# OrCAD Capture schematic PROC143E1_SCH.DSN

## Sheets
1 05. ACCESSORIES: title: HARDWARE SCHEMATICS; rev: E1
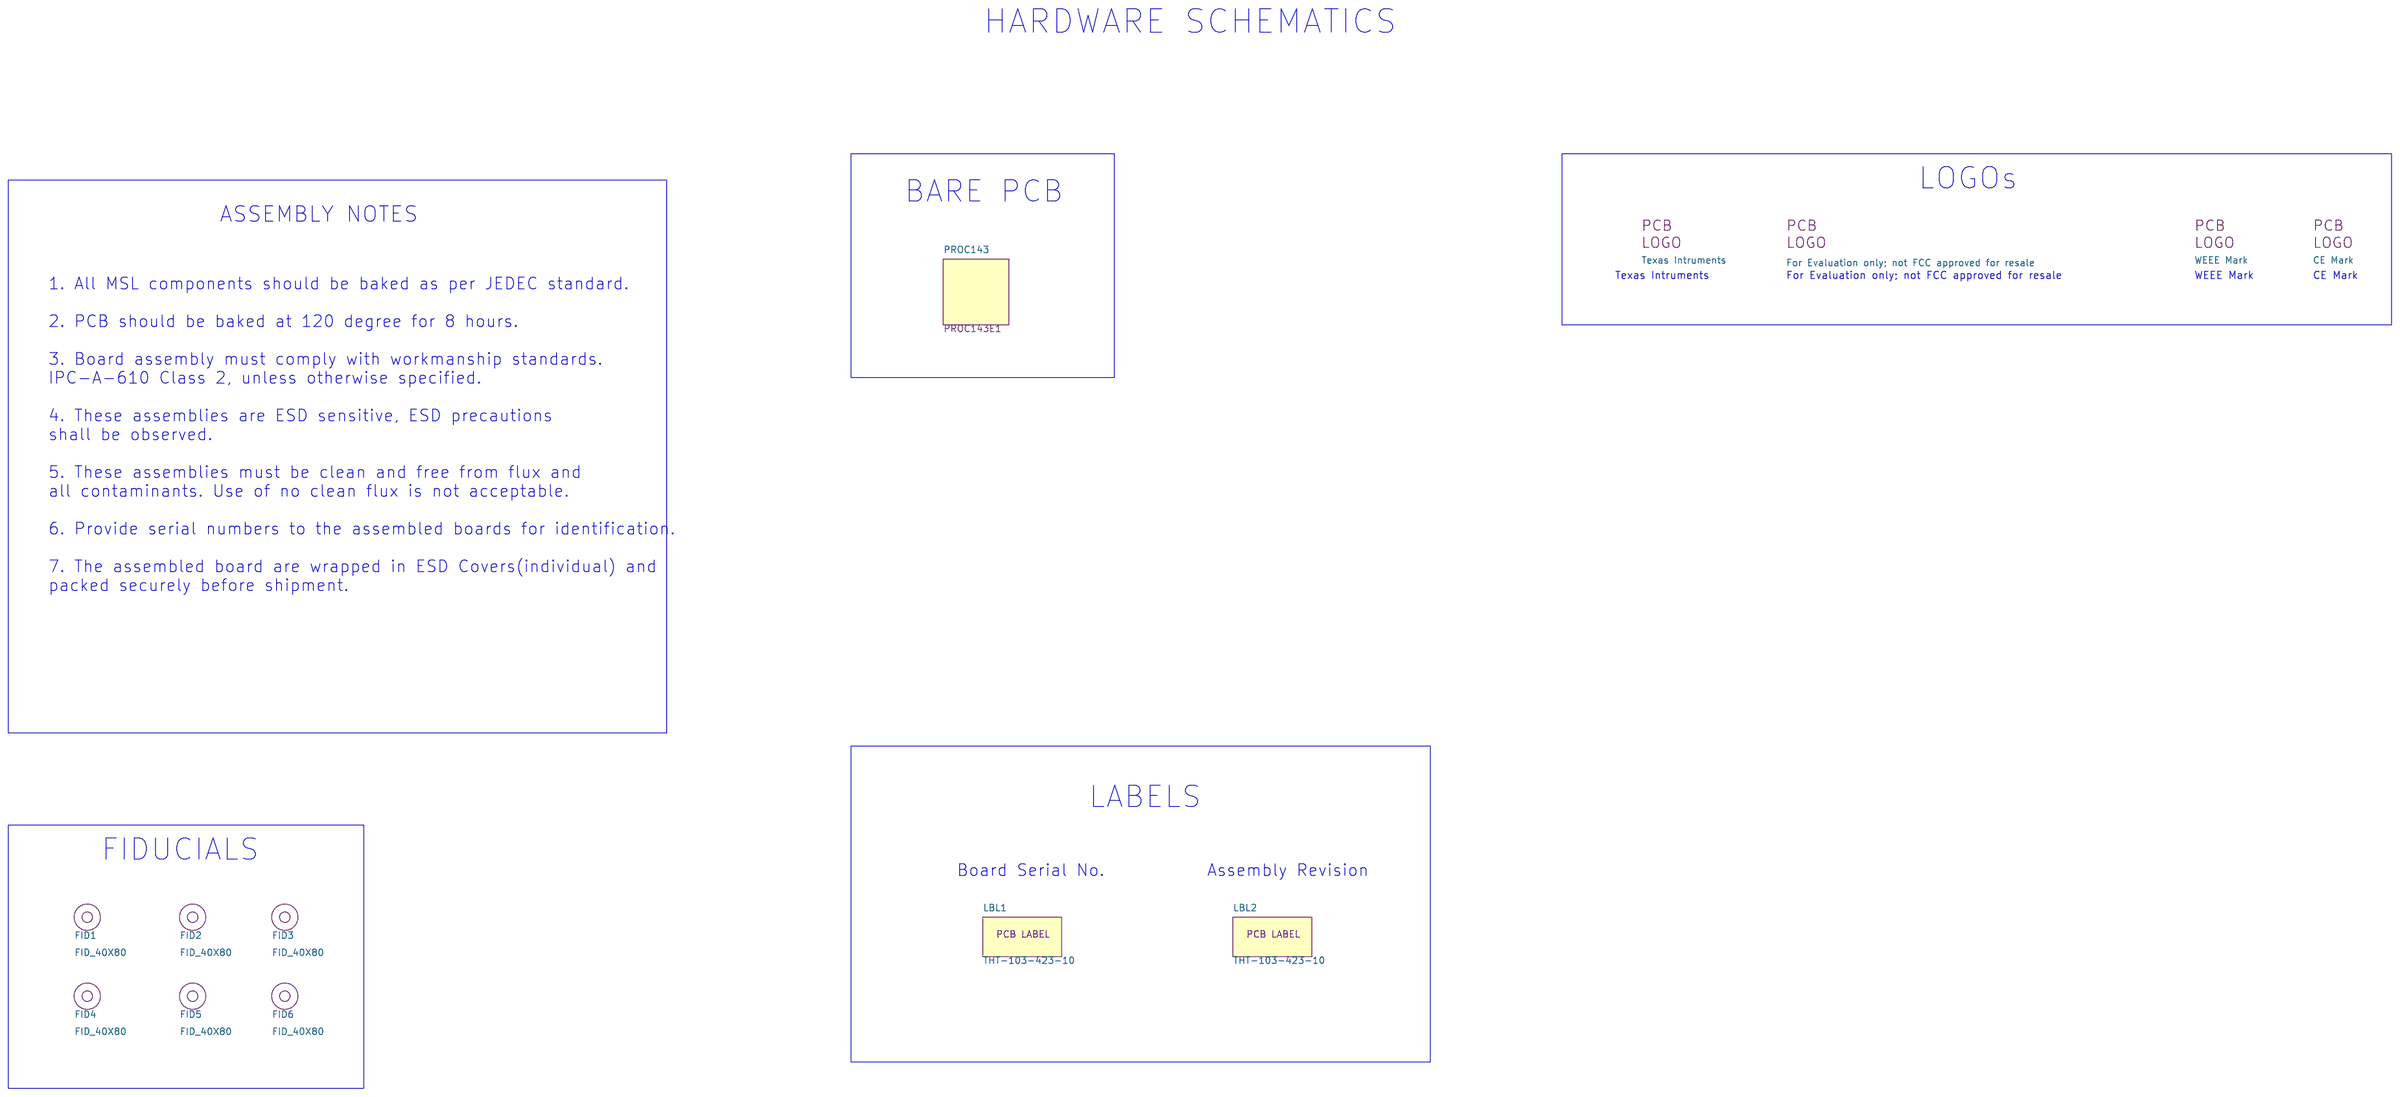
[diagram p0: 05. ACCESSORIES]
2 01. TABLE OF CONTENTS: title: TABLE OF CONTENTS
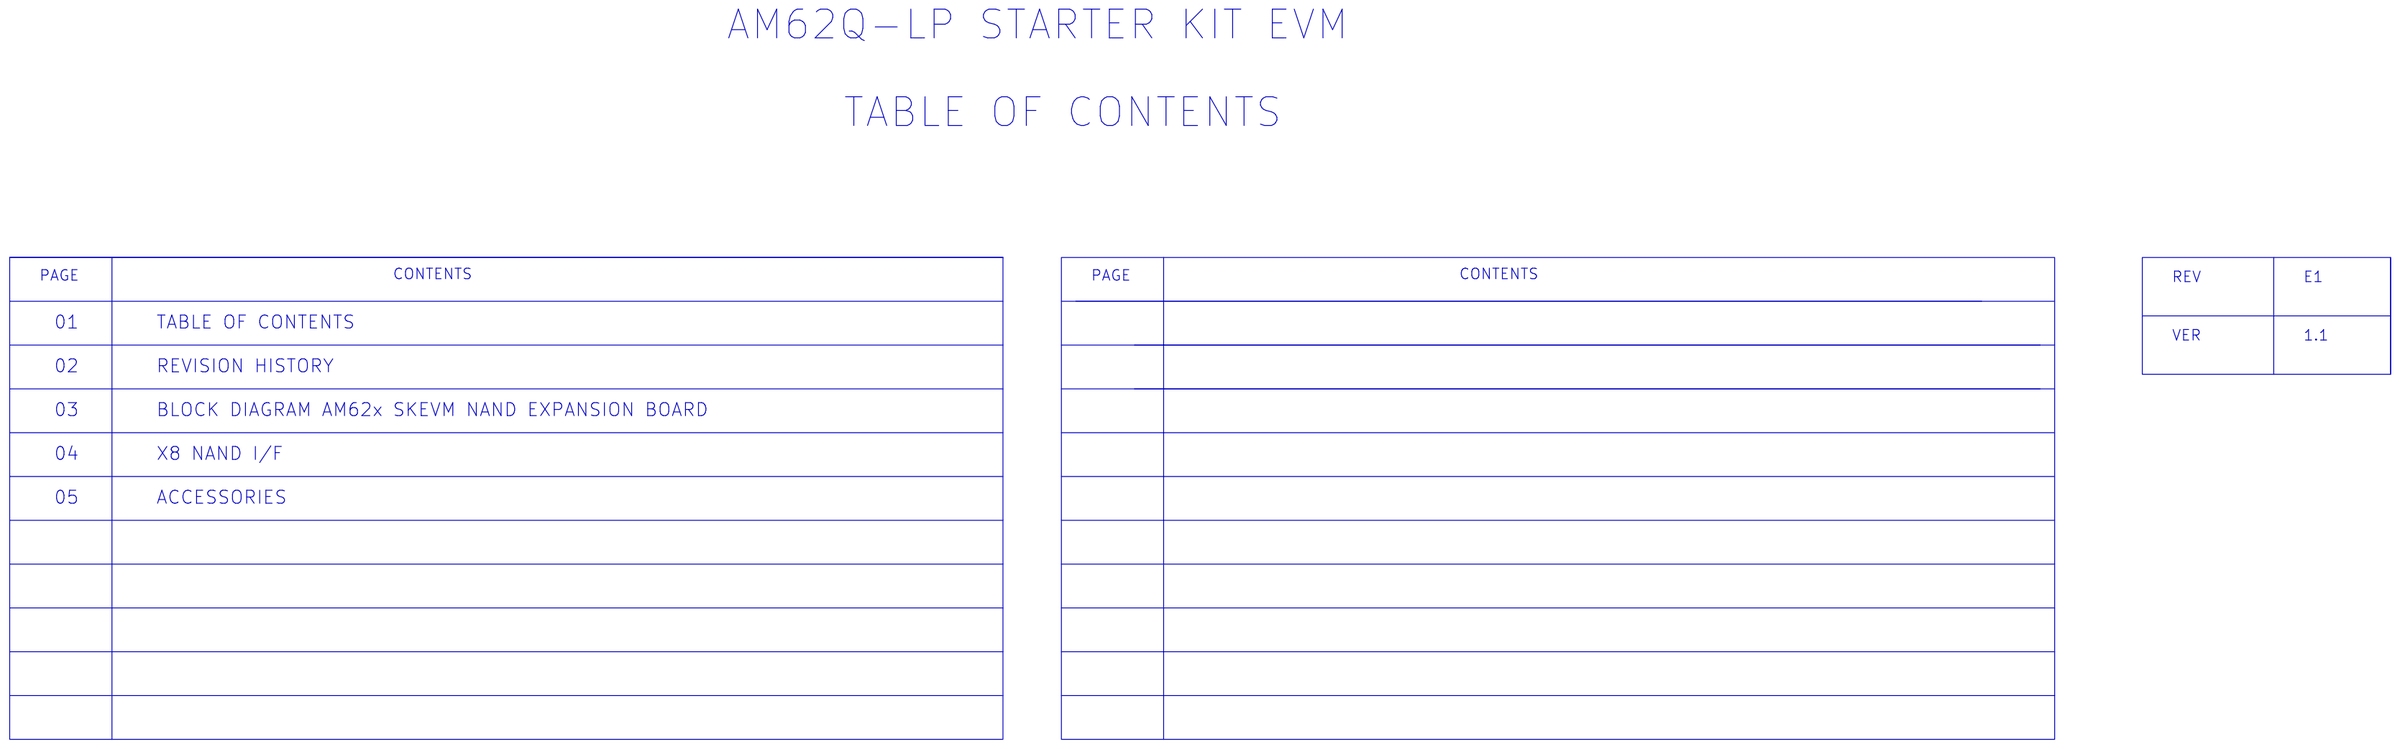
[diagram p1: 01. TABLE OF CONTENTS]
3 02. REVISION HISTORY: title: REVISION HISTORY
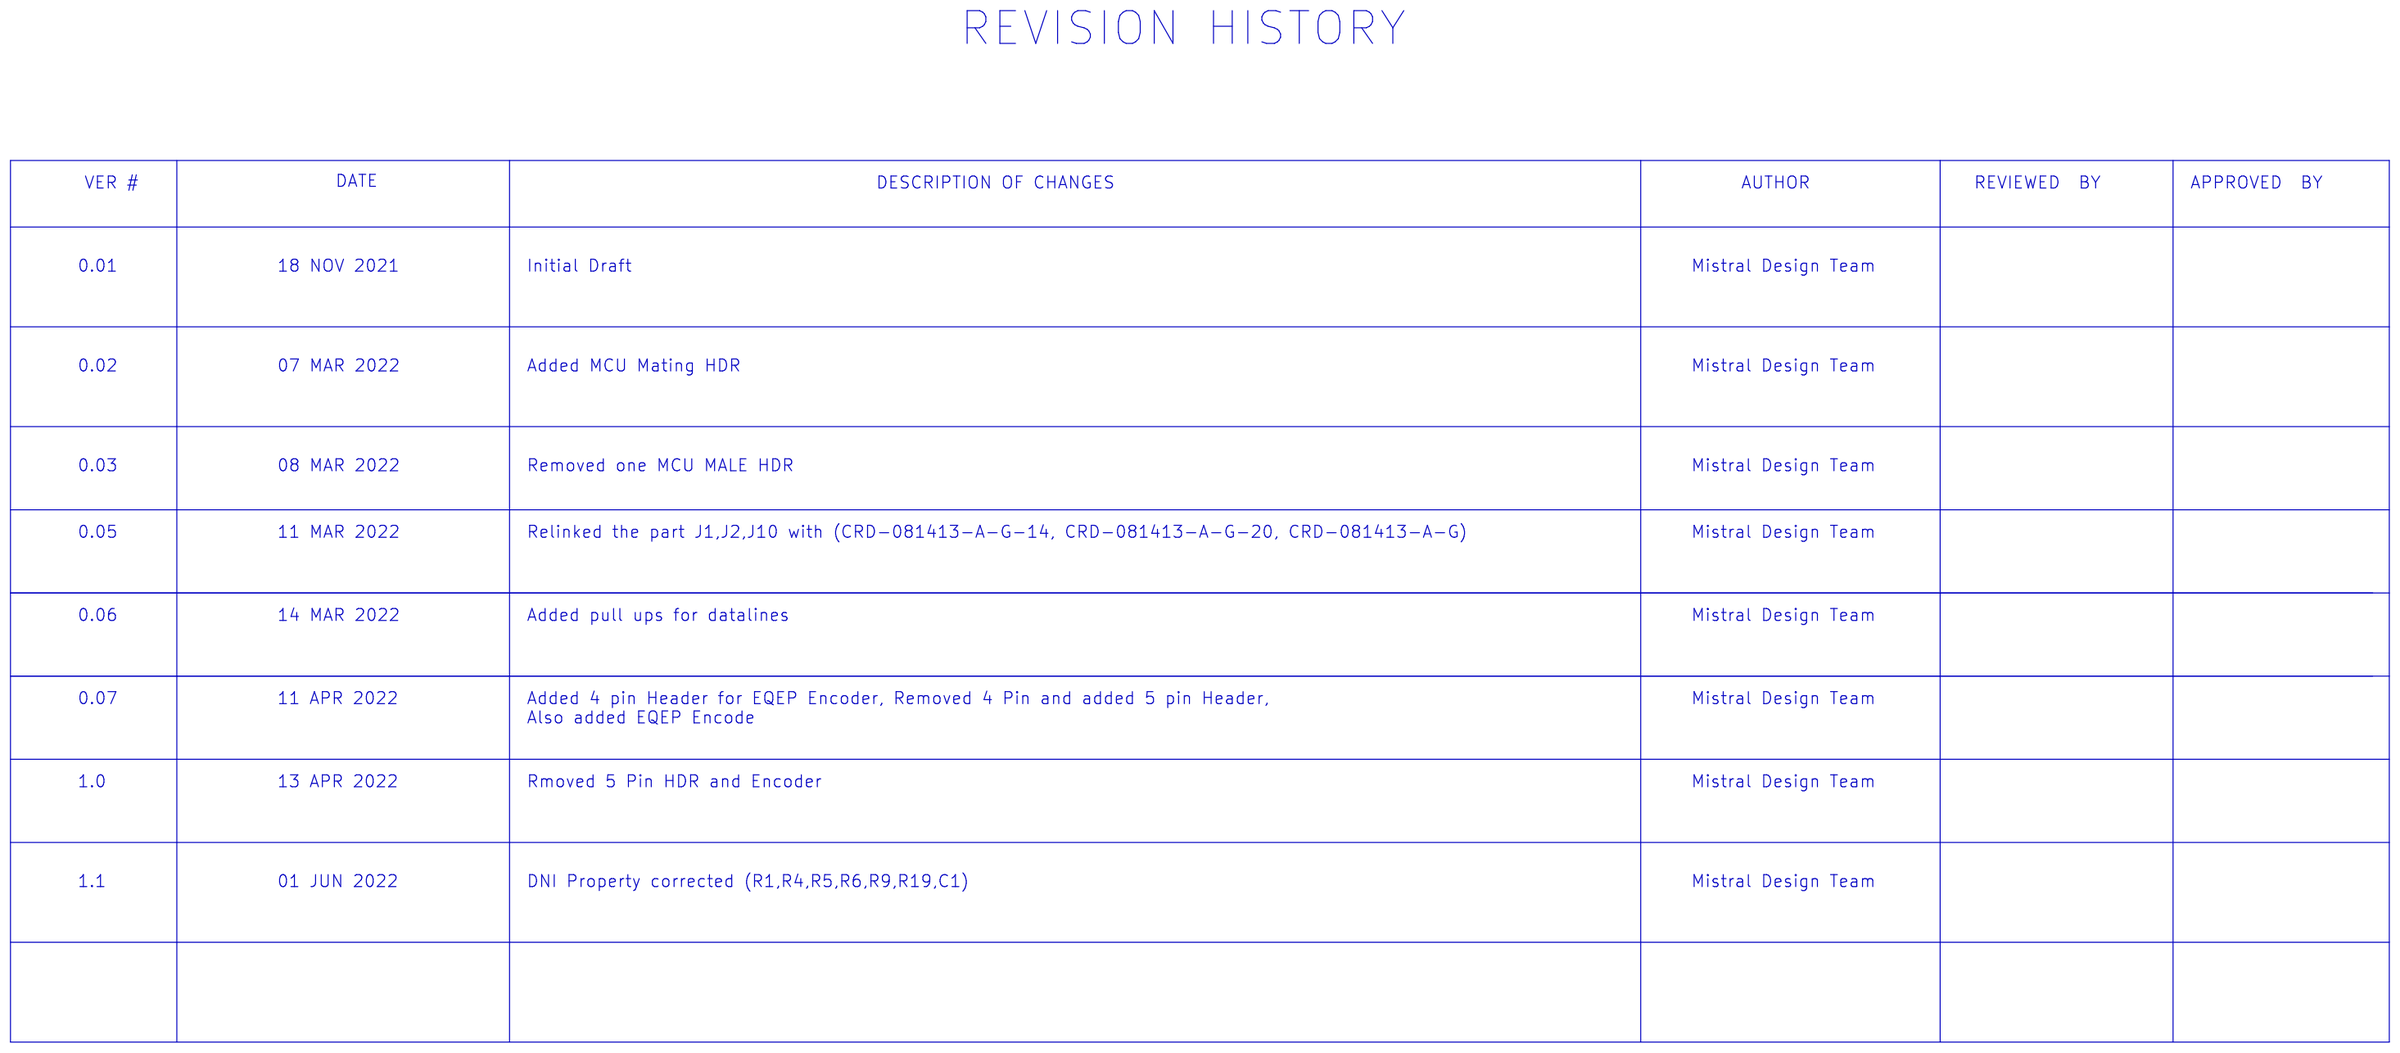
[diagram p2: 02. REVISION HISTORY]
4 03. BLOCK DGM AM62Q-LP-SKEVM: title: BLOCK DIAGRAM x8 NAND
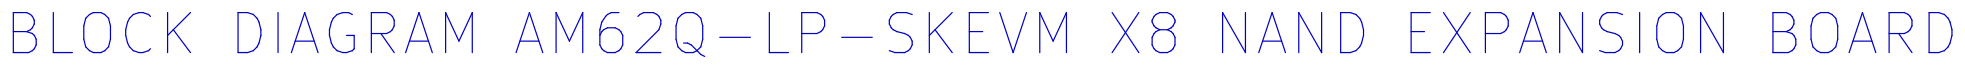
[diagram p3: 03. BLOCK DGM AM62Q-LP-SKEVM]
5 04. X8 NAND I/F: size C; title: x8 NAND
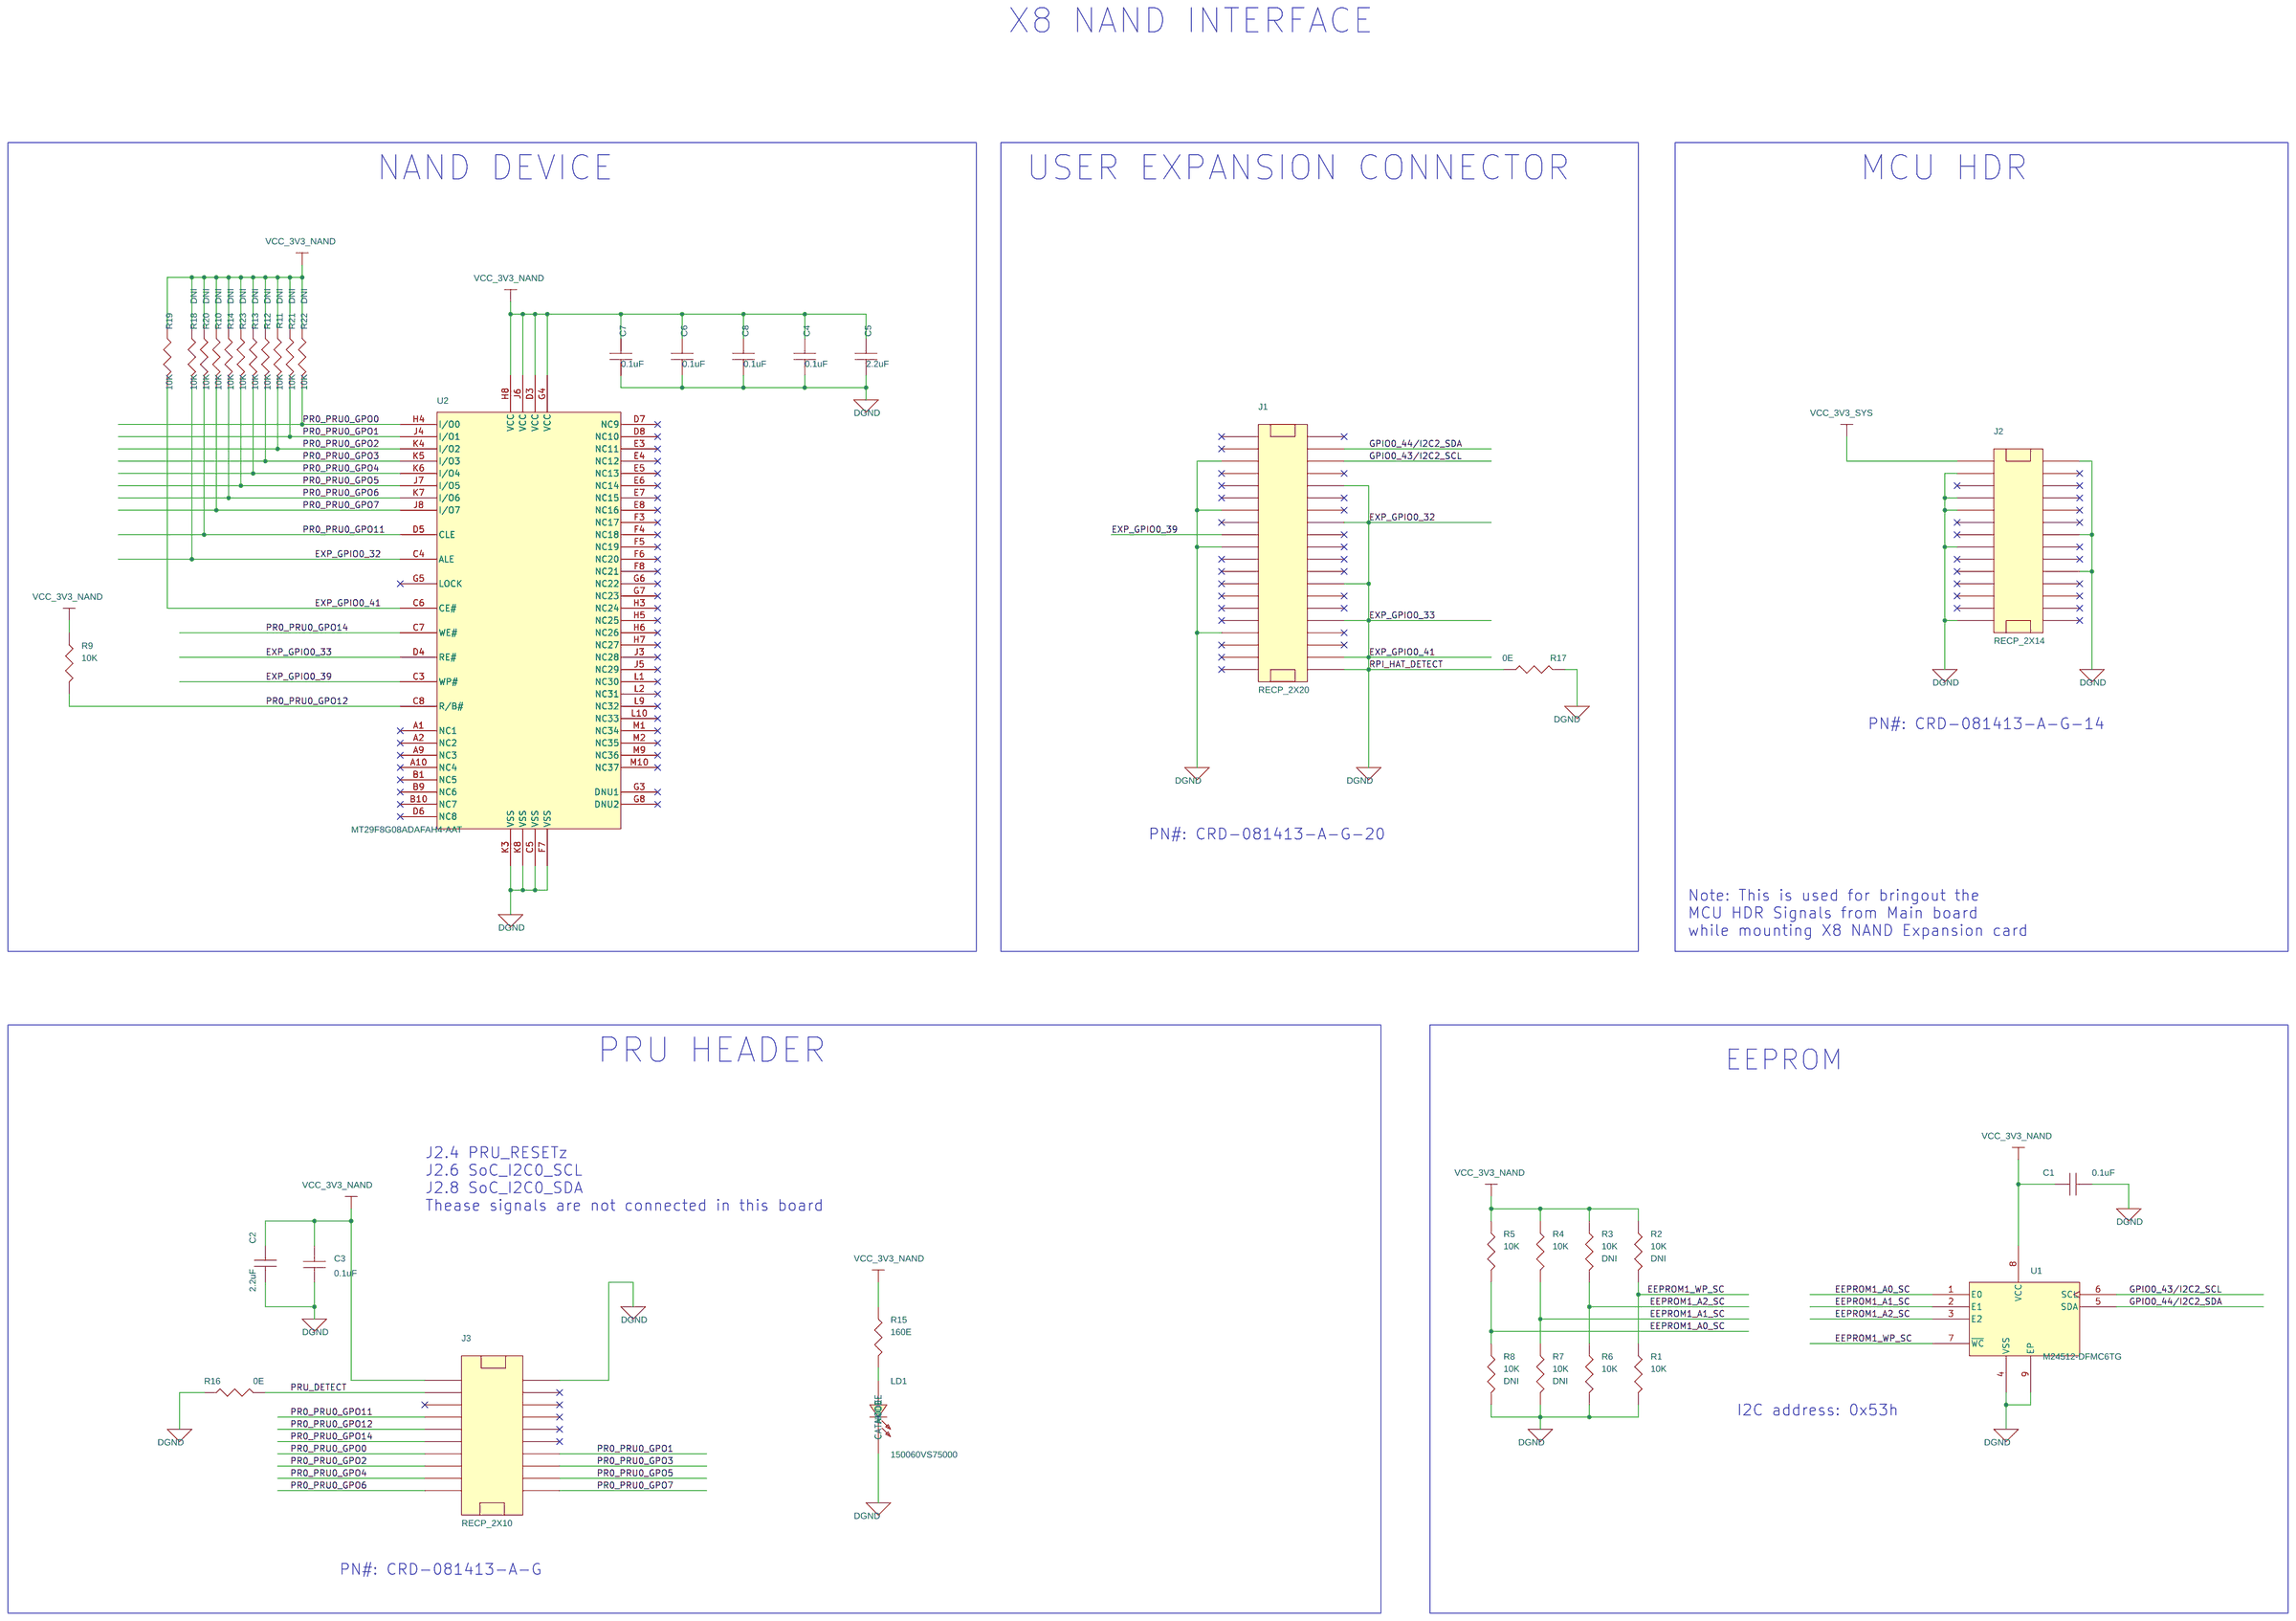
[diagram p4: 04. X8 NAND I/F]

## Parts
sheet 04. X8 NAND I/F
C1  0.1uF  [CAP0402_0-75]
C2  2.2uF  [CAP0402_0-75]
C3  0.1uF  [CAP0402_0-75]
C4  0.1uF  [CAP0402_0-75]
C5  2.2uF  [CAP0402_0-75]
C6  0.1uF  [CAP0402_0-75]
C7  0.1uF  [CAP0402_0-75]
C8  0.1uF  [CAP0402_0-75]
J1  RECP_2X20  [RECPT_2X20_CRD-081413-A-20_S_T_8-6]
J2  RECP_2X14  [RECPT_2X14_CRD-081413-A-14_S_T_8-6]
J3  RECP_2X10  [RECPT_2X10_CRD-081413-A_S_T_8-6]
LD1  150060VS75000  [LED_150060SS75000_70X40_SMD_0-8]
R1  10K  [RES0402_0-5]
R2  10K  [RES0402_0-5]
R3  10K  [RES0402_0-5]
R4  10K  [RES0402_0-5]
R5  10K  [RES0402_0-5]
R6  10K  [RES0402_0-5]
R7  10K  [RES0402_0-5]
R8  10K  [RES0402_0-5]
R9  10K  [RES0402_0-5]
R10  10K  [RES0402_0-5]
R11  10K  [RES0402_0-5]
R12  10K  [RES0402_0-5]
R13  10K  [RES0402_0-5]
R14  10K  [RES0402_0-5]
R15  160E  [RES0603_0-75]
R16  0E  [RES0201_0-5]
R17  0E  [RES0201_0-5]
R18  10K  [RES0402_0-5]
R19  10K  [RES0402_0-5]
R20  10K  [RES0402_0-5]
R21  10K  [RES0402_0-5]
R22  10K  [RES0402_0-5]
R23  10K  [RES0402_0-5]
U1  M24512-DFMC6TG  [UFDFPN8_M24512_120X80_0-6]
U2  MT29F8G08ADAFAH4-AAT  [FBGA63_31-49_360X440_1]
sheet 05. ACCESSORIES
FID1  FID_40X80  [FID_40X80]
FID2  FID_40X80  [FID_40X80]
FID3  FID_40X80  [FID_40X80]
FID4  FID_40X80  [FID_40X80]
FID5  FID_40X80  [FID_40X80]
FID6  FID_40X80  [FID_40X80]
LBL1  THT-103-423-10  [NA]
LBL2  THT-103-423-10  [NA]
LOGO1  Texas Intruments  [TI_Stacked_Overlay_Small]
LOGO2  For Evaluation only; not FCC approved for resale  [FCC_disclaimer]
LOGO3  WEEE Mark  [TI_Stacked_Overlay_Small]
LOGO4  CE Mark  [TI_Stacked_Overlay_Small]
PCB1  PROC143

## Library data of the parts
C1 C3 C4 C6-C8 = CAP: CAP CERAMIC 0.1uF 25V 20% X5R 0402; Chkd/date: MANIRAJA/170820; Crtd /date: ALVY/170820; Custom_Duty: 15%; Customs_HS_Code: 85322990; Distributor_name: DIGIKEY; Distributor_part_number: 732-7495-1-ND; Footprint Path: Y:\MIS_DATABASE\Library\ALTIUM_TOOL\PCB_FOOTPRINTS\Altium_Footprint_Lib.PcbLib; Height: 0.55MM; Library Path: Y:\MIS_DATABASE\Library\ALTIUM_TOOL\SCHEMATICS_PARTS\MS_DISCRETE_Library.schlib; Mfr_name: WURTH ELECTRONICS; Mfr_part_number: 885012105018; Mistral Part No: 120020080003-R; Package: 0402; Part_type: CAPACITORS\CERAMIC; Project: AM64x_EVM_BRD; RoHS: RoHS; Temperature: -55°C+85°C; Tolerance: 20%; Voltage: 25V; Wattage: NA; Weight: 0.65mg; Datasheet: Y:\MIS_DATABASE\DATASHEETS\CAPACITORS\885012105018.PDF
C2 C5 = CAP: CAP CERAMIC 2.2uF 25V 10% X5R 0402; Chkd/date: ALVY/010721; Crtd /date: MANIRAJA/010721; Custom_Duty: 15%; Customs_HS_Code: 85322990; Distributor_name: DIGIKEY; Distributor_part_number: 490-12703-1-ND; Footprint Path: Y:\MIS_DATABASE\Library\ALTIUM_TOOL\PCB_FOOTPRINTS\Altium_Footprint_Lib.PcbLib; Height: 0.70MM; Library Path: Y:\MIS_DATABASE\Library\ALTIUM_TOOL\SCHEMATICS_PARTS\MS_DISCRETE_Library.schlib; Mfr_name: MURATA; Mfr_part_number: GRM155R61E225KE11D; Mistral Part No: 120015120001-R; Package: 0402; Part_type: CAPACITORS\CERAMIC; Project: TI_AM263X_CC; RoHS: RoHS; Temperature: -55°C+85°C; Tolerance: 10%; Voltage: 25V; Wattage: NA; Weight: 1.5mg; Datasheet: Y:\MIS_DATABASE\DATASHEETS\CAPACITORS\GRM155R61E225KE11.PDF
J1 = RECP_20X2: CON RECP 2X20 2.54MM PITCH ST TH; Chkd/date: ALVY/110322; Crtd /date: TAMILARASU/100322; Custom_Duty: 24%; Customs_HS_Code: 85369090; Distributor_name: NA; Distributor_part_number: NA; Footprint Path: Y:\MIS_DATABASE\Library\ALTIUM_TOOL\PCB_FOOTPRINTS\Altium_Footprint_Lib.PcbLib; Height: 8.51MM; Library Path: Y:\MIS_DATABASE\Library\ALTIUM_TOOL\SCHEMATICS_PARTS\MS_CONNECTOR_Library.schlib; Mfr_name: MAJOR LEAGUE; Mfr_part_number: CRD-081413-A-G-20; Mistral Part No: 150022030011-R; Package: THRU-HOLE; Part_type: CONNECTOR\RECEPTACLE; Project: TI_AM62Q_SKEVM_xNAND_BRD; RoHS: RoHS; Temperature: -40°C+105°C; Tolerance: NA; Voltage: NA; Wattage: NA; Weight: NA; Datasheet: Y:\MIS_DATABASE\DATASHEETS\CONNECTORS\CRD-081413-A-XX.PDF
J2 = RECP_14X2: CON RECP 2X14 2.54MM PITCH ST TH; Chkd/date: ALVY/110322; Crtd /date: TAMILARASU/100322; Custom_Duty: 24%; Customs_HS_Code: 85369090; Distributor_name: NA; Distributor_part_number: NA; Footprint Path: Y:\MIS_DATABASE\Library\ALTIUM_TOOL\PCB_FOOTPRINTS\Altium_Footprint_Lib.PcbLib; Height: 8.51MM; Library Path: Y:\MIS_DATABASE\Library\ALTIUM_TOOL\SCHEMATICS_PARTS\MS_CONNECTOR_Library.schlib; Mfr_name: MAJOR LEAGUE; Mfr_part_number: CRD-081413-A-G-14; Mistral Part No: 150022030012-R; Package: THRU-HOLE; Part_type: CONNECTOR\RECEPTACLE; Project: TI_AM62Q_SKEVM_xNAND_BRD; RoHS: RoHS; Temperature: -40°C+105°C; Tolerance: NA; Voltage: NA; Wattage: NA; Weight: NA; Datasheet: Y:\MIS_DATABASE\DATASHEETS\CONNECTORS\CRD-081413-A.PDF
J3 = RECP_10X2: CON RECP 2X10 2.54MM PITCH ST TH; Chkd/date: MANIRAJA/231120; Crtd /date: ALVY/201120; Custom_Duty: 24%; Customs_HS_Code: 85369090; Distributor_name: NA; Distributor_part_number: NA; Footprint Path: Y:\MIS_DATABASE\Library\ALTIUM_TOOL\PCB_FOOTPRINTS\Altium_Footprint_Lib.PcbLib; Height: 8.51MM; Library Path: Y:\MIS_DATABASE\Library\ALTIUM_TOOL\SCHEMATICS_PARTS\MS_CONNECTOR_Library.schlib; Mfr_name: MAJOR LEAGUE; Mfr_part_number: CRD-081413-A-G; Mistral Part No: 150020110025-R; Package: THRU-HOLE; Part_type: CONNECTOR\RECEPTACLE; Project: TI_AM243x LP EVM; RoHS: RoHS; Temperature: -40°C+105°C; Tolerance: NA; Voltage: NA; Wattage: NA; Weight: NA; Datasheet: Y:\MIS_DATABASE\DATASHEETS\CONNECTORS\CRD-081413-A.PDF
LD1 = DIODE_LED: DIODE LED BRIGHT GREEN SMD; Chkd/date: MANIRAJA/220720; Crtd /date: ALVY/210720; Custom_Duty: 24%; Customs_HS_Code: 85439000; Distributor_name: DIGIKEY; Distributor_part_number: 732-4980-1-ND; Footprint Path: Y:\MIS_DATABASE\Library\ALTIUM_TOOL\PCB_FOOTPRINTS\Altium_Footprint_Lib.PcbLib; Height: 0.80MM; Library Path: Y:\MIS_DATABASE\Library\ALTIUM_TOOL\SCHEMATICS_PARTS\MS_OPTO_Library.schlib; Mfr_name: WURTH ELECTRONICS; Mistral Part No: 130020070019-R; Package: SMD; Part_type: OPTO\LED; Project: AM64x-IO LINK BRD; RoHS: RoHS; Temperature: -40°C+85°C; Tolerance: NA; Voltage: NA; Wattage: NA; Weight: 25mg; Datasheet: Y:\MIS_DATABASE\DATASHEETS\DISCRETES\LEDS\150060VS75000.PDF
R1 R4-R6 R9 R19 = RESISTOR: RES 10K 1/16W 5% 0402; Chkd/date: VASANTHA/061216; Crtd /date: MAZHAR/230805; Custom_Duty: 15%; Customs_HS_Code: 85332119; Distributor_name: DIGIKEY; Distributor_part_number: 311-10KJRCT-ND; Footprint Path: Y:\MIS_DATABASE\Library\ALTIUM_TOOL\PCB_FOOTPRINTS\Altium_Footprint_Lib.PcbLib; Height: 0.40MM; Library Path: Y:\MIS_DATABASE\Library\ALTIUM_TOOL\SCHEMATICS_PARTS\MS_DISCRETE_Library.schlib; Mfr_name: YAGEO AMERICA; Mfr_part_number: RC0402JR-0710KL; Mistral Part No: 110009030208-R; Package: 0402; Part_type: RESISTORS\FIXED; Project: HSE; RoHS: Pb-Free; Temperature: -55°C+155°C; Tolerance: 5%; Voltage: NA; Wattage: 1/16W; Weight: 0.65mg; Datasheet: Y:\MIS_DATABASE\DATASHEETS\RESISTORS\YAGEO-RC0402.PDF
R2 R3 R7 R8 R10-R14 R18 R20-R23 = RESISTOR: RES 10K 1/16W 5% 0402; Assembly_Instruction: DNI; Chkd/date: VASANTHA/061216; Crtd /date: MAZHAR/230805; Custom_Duty: 15%; Customs_HS_Code: 85332119; Distributor_name: DIGIKEY; Distributor_part_number: 311-10KJRCT-ND; Footprint Path: Y:\MIS_DATABASE\Library\ALTIUM_TOOL\PCB_FOOTPRINTS\Altium_Footprint_Lib.PcbLib; Height: 0.40MM; Library Path: Y:\MIS_DATABASE\Library\ALTIUM_TOOL\SCHEMATICS_PARTS\MS_DISCRETE_Library.schlib; Mfr_name: YAGEO AMERICA; Mfr_part_number: RC0402JR-0710KL; Mistral Part No: 110009030208-R; Package: 0402; Part_type: RESISTORS\FIXED; Project: HSE; RoHS: Pb-Free; Temperature: -55°C+155°C; Tolerance: 5%; Voltage: NA; Wattage: 1/16W; Weight: 0.65mg; Datasheet: Y:\MIS_DATABASE\DATASHEETS\RESISTORS\YAGEO-RC0402.PDF
R15 = RESISTOR: RES 160E 1/10W 5% 0603; Chkd/date: NAVEED/040915; Crtd /date: NAVEED/040915; Custom_Duty: 15%; Customs_HS_Code: 85332119; Distributor_name: DIGIKEY; Distributor_part_number: P160GCT-ND; Footprint Path: Y:\MIS_DATABASE\Library\ALTIUM_TOOL\PCB_FOOTPRINTS\Altium_Footprint_Lib.PcbLib; Height: 0.55MM; Library Path: Y:\MIS_DATABASE\Library\ALTIUM_TOOL\SCHEMATICS_PARTS\MS_DISCRETE_Library.schlib; Mfr_name: PANASONIC-ECG; Mfr_part_number: ERJ-3GEYJ161V; Mistral Part No: 110015090009-R; Package: 0603; Part_type: RESISTORS\FIXED; Project: PEEL_IR_DONGLE; RoHS: RoHS; Temperature: -55°C+155°C; Tolerance: 5%; Voltage: NA; Wattage: 1/10W; Weight: 2mg; Datasheet: Y:\MIS_DATABASE\DATASHEETS\RESISTORS\PAN-ERJSER_NOV17.PDF
R16 R17 = RESISTOR: RES 0E 1/20W JUMPER 0201; Chkd/date: VASANTHA/061216; Crtd /date: MAZHAR/040505; Custom_Duty: 15%; Customs_HS_Code: 85332119; Distributor_name: DIGIKEY; Distributor_part_number: P0.0AGCT-ND; Footprint Path: Y:\MIS_DATABASE\Library\ALTIUM_TOOL\PCB_FOOTPRINTS\Altium_Footprint_Lib.PcbLib; Height: 0.26MM; Library Path: Y:\MIS_DATABASE\Library\ALTIUM_TOOL\SCHEMATICS_PARTS\MS_DISCRETE_Library.schlib; Mfr_name: PANASONIC-ECG; Mfr_part_number: ERJ-1GE0R00C; Mistral Part No: 110009030078-R; Package: 0201; Part_type: RESISTORS\FIXED; Project: HS100RD; RoHS: RoHS; Temperature: -55°C+125°C; Tolerance: NA; Voltage: NA; Wattage: 1/20W; Weight: 0.15mg; Datasheet: Y:\MIS_DATABASE\DATASHEETS\RESISTORS\PAN-ERJXGE-FEB06.PDF
U1 = M24512_UFDFPN8: IC 1.7-5.5V 512Kb I2C SERIAL EEPROM UFDFPN8; Chkd/date: ALVY/240322; Crtd /date: ALVY/240322; Custom_Duty: 15%; Customs_HS_Code: 85423100; Distributor_name: DIGIKEY; Distributor_part_number: 497-15745-1-ND; Footprint Path: Y:\MIS_DATABASE\Library\ALTIUM_TOOL\PCB_FOOTPRINTS\Altium_Footprint_Lib.PcbLib; Height: 0.60MM; Library Path: Y:\MIS_DATABASE\Library\ALTIUM_TOOL\SCHEMATICS_PARTS\MS_MISCMEMORY_Library.schlib; Mfr_name: ST MICROELECTRONICS; Mistral Part No: 141122030005-R; Package: UFDFPN8; Part_type: ICS\DIGITAL\MEMORY; Project: TI_SK-AM62Q-LP EVM_BRD; RoHS: RoHS; Temperature: -40°C+85°C; Tolerance: NA; Voltage: NA; Wattage: NA; Weight: 16mg; Datasheet: Y:\MIS_DATABASE\DATASHEETS\ICS\MEMORY\M24512-W-R-DF.PDF
U2 = MT29F8G08ADAFAH4_VFBAG63: IC 3.3V 8Gb NAND FLASH MEMORY VFBGA63; Chkd/date: MANIRAJA/260721; Crtd /date: ALVY/260721; Custom_Duty: 15%; Customs_HS_Code: 85423100; Distributor_name: NA; Distributor_part_number: NA; Footprint Path: Y:\MIS_DATABASE\Library\ALTIUM_TOOL\PCB_FOOTPRINTS\Altium_Footprint_Lib.PcbLib; Height: 1.00MM; Library Path: Y:\MIS_DATABASE\Library\ALTIUM_TOOL\SCHEMATICS_PARTS\MS_MISCMEMORY_Library.schlib; Mfr_name: MICRON; Mfr_part_number: MT29F8G08ADAFAH4-AAT:F; Mistral Part No: 141121070004-R; Package: VFBGA63; Part_type: ICS\DIGITAL\MEMORY; Project: AM64x HSE NAND BRD; RoHS: RoHS; Temperature: -40°C+105°C; Tolerance: NA; Voltage: NA; Wattage: NA; Weight: NA; Datasheet: Y:\MIS_DATABASE\DATASHEETS\ICS\MEMORY\MT29F8G08ADAFXX.PDF
FID1-FID6 = Fiducial
LBL1 LBL2 = ACCESSORY_THT-3-423-10: ACCESSORIE 1 WORKHORSE POLYSTER LABLE 0.25" X 1"; Chkd/date: MANIRAJA/270218; Crtd /date: ALVY/260218; Footprint Path: Y:\MIS_DATABASE\Library\ALTIUM_TOOL\PCB_FOOTPRINTS\Altium_Footprint_Lib.PcbLib; Library Path: Y:\MIS_DATABASE\Library\ALTIUM_TOOL\SCHEMATICS_PARTS\MS_MECHANICAL_Library.schlib; Mfr_name: BRADY; Mistral Part No: 160018020185; Part_type: ACCESSORIES; Project: TI_MAXIE_CPB
LOGO1 LOGO3 LOGO4 = TI_Logo
LOGO2 = FCC_disclaimer
PCB1 = PCB: x8 NAND Card Bare PCB; Mfr_part_number: PROC143E1; Mistral Part No: FY21-22/01986000201

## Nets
DGND: C1.2 C2.2 C3.1 C4.2 C5.2 C6.2 C7.2 C8.2 J1.6 J1.9 J1.14 J1.20 J1.25 J1.34 J2.2 J2.3 J2.7 J2.9 J2.14 J2.15 J2.20 J2.27 J3.2 LD1.1(CATHODE) R1.2 R6.2 R7.2 R8.2 R16.1 R17.1 U1.4(VSS) U1.9(EP) U2.C5(VSS) U2.F7(VSS) U2.K3(VSS) U2.K8(VSS)
VCC_3V3_NAND: C1.1 C2.1 C3.2 C4.1 C5.1 C6.1 C7.1 C8.1 J3.1 R2.1 R3.1 R4.1 R5.1 R9.1 R10.1 R11.1 R12.1 R13.1 R14.1 R15.1 R18.1 R19.1 R20.1 R21.1 R22.1 R23.1 U1.8(VCC) U2.D3(VCC) U2.G4(VCC) U2.H8(VCC) U2.J6(VCC)
VCC_3V3_SYS: J2.1
EEPROM1_A0_SC: R5.2 R8.1 U1.1(E0)
EEPROM1_A1_SC: R4.2 R7.1 U1.2(E1)
EEPROM1_A2_SC: R3.2 R6.1 U1.3(E2)
EEPROM1_WP_SC: R1.1 R2.2 U1.7(~{WC})
EXP_GPIO0_32: J1.15 R18.2 U2.C4(ALE)
EXP_GPIO0_33: J1.31 U2.D4(RE#)
EXP_GPIO0_39: J1.18 U2.C3(WP#)
EXP_GPIO0_41: J1.37 R19.2 U2.C6(CE#)
GPIO0_43/I2C2_SCL: J1.5 U1.6(SCL)
GPIO0_44/I2C2_SDA: J1.3 U1.5(SDA)
PR0_PRU0_GPO0: J3.13 R22.2 U2.H4(I/O0)
PR0_PRU0_GPO1: J3.14 R21.2 U2.J4(I/O1)
PR0_PRU0_GPO2: J3.15 R11.2 U2.K4(I/O2)
PR0_PRU0_GPO3: J3.16 R12.2 U2.K5(I/O3)
PR0_PRU0_GPO4: J3.17 R13.2 U2.K6(I/O4)
PR0_PRU0_GPO5: J3.18 R23.2 U2.J7(I/O5)
PR0_PRU0_GPO6: J3.19 R14.2 U2.K7(I/O6)
PR0_PRU0_GPO7: J3.20 R10.2 U2.J8(I/O7)
PR0_PRU0_GPO11: J3.7 R20.2 U2.D5(CLE)
PR0_PRU0_GPO12: J3.9 R9.2 U2.C8(R/B#)
PR0_PRU0_GPO14: J3.11 U2.C7(WE#)
PRU_DETECT: J3.3 R16.2
RPI_HAT_DETECT: J1.39 R17.2
N19755073: LD1.2(ANODE) R15.2

Not connected (* = marked no-connect by the designer): J1 1* 2* 4* 7* 8* 10* 11* 12* 13* 16* 17* 19* 21* 22* 23* 24* 26* 27* 28* 29* 30* 32* 33* 35* 36* 38* 40*; J2 4* 5* 6* 8* 10* 11* 12* 13* 16* 17* 18* 19* 21* 22* 23* 24* 25* 26* 28*; J3 4* 5* 6* 8* 10* 12*; U2 A1(NC1)* A2(NC2)* A9(NC3)* A10(NC4)* B1(NC5)* B9(NC6)* B10(NC7)* D6(NC8)* D7(NC9)* D8(NC10)* E3(NC11)* E4(NC12)* E5(NC13)* E6(NC14)* E7(NC15)* E8(NC16)* F3(NC17)* F4(NC18)* F5(NC19)* F6(NC20)* F8(NC21)* G3(DNU1)* G5(LOCK)* G6(NC22)* G7(NC23)* G8(DNU2)* H3(NC24)* H5(NC25)* H6(NC26)* H7(NC27)* J3(NC28)* J5(NC29)* L1(NC30)* L2(NC31)* L9(NC32)* L10(NC33)* M1(NC34)* M2(NC35)* M9(NC36)* M10(NC37)*

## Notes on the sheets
sheet 1
- HARDWARE SCHEMATICS
- LOGOs
- BARE PCB
- ASSEMBLY NOTES
- 1. All MSL components should be baked as per JEDEC standard.
  2. PCB should be baked at 120 degree for 8 hours.
  3. Board assembly must comply with workmanship standards.
  IPC-A-610 Class 2, unless otherwise specified.
  4. These assemblies are ESD sensitive, ESD precautions
  shall be observed.
  5. These assemblies must be clean and free from flux and
  all contaminants. Use of no clean flux is not acceptable.
  6. Provide serial numbers to the assembled boards for identification.
  7. The assembled board are wrapped in ESD Covers(individual) and
  packed securely before shipment.
- Texas Intruments
- For Evaluation only; not FCC approved for resale
- WEEE Mark
- CE Mark
- LABELS
- FIDUCIALS
- Board Serial No.
- Assembly Revision
sheet 2
- AM62Q-LP STARTER KIT EVM
- TABLE OF CONTENTS
- PAGE
- CONTENTS
- PAGE
- CONTENTS
- REV
- E1
- 01
- TABLE OF CONTENTS
- VER
- 1.1
- 02
- REVISION HISTORY
- 03
- BLOCK DIAGRAM AM62x SKEVM NAND EXPANSION BOARD
- 04
- X8 NAND I/F
- 05
- ACCESSORIES
sheet 3
- REVISION HISTORY
- VER #
- DATE
- DESCRIPTION OF CHANGES
- AUTHOR
- REVIEWED  BY
- APPROVED  BY
- 0.01
- 18 NOV 2021
- Initial Draft
- Mistral Design Team
- 0.02
- 07 MAR 2022
- Added MCU Mating HDR
- Mistral Design Team
- 0.03
- 08 MAR 2022
- Removed one MCU MALE HDR
- Mistral Design Team
- 0.05
- 11 MAR 2022
- Relinked the part J1,J2,J10 with (CRD-081413-A-G-14, CRD-081413-A-G-20, CRD-081413-A-G)
- Mistral Design Team
- 0.06
- 14 MAR 2022
- Added pull ups for datalines
- Mistral Design Team
- 0.07
- 11 APR 2022
- Added 4 pin Header for EQEP Encoder, Removed 4 Pin and added 5 pin Header,
  Also added EQEP Encode
- Mistral Design Team
- 1.0
- 13 APR 2022
- Rmoved 5 Pin HDR and Encoder
- Mistral Design Team
- 1.1
- 01 JUN 2022
- DNI Property corrected (R1,R4,R5,R6,R9,R19,C1)
- Mistral Design Team
sheet 4
- BLOCK DIAGRAM AM62Q-LP-SKEVM X8 NAND EXPANSION BOARD
sheet 5
- X8 NAND INTERFACE
- NAND DEVICE
- USER EXPANSION CONNECTOR
- MCU HDR
- PN#: CRD-081413-A-G-14
- PN#: CRD-081413-A-G-20
- Note: This is used for bringout the
  MCU HDR Signals from Main board
  while mounting X8 NAND Expansion card
- PRU HEADER
- EEPROM
- J2.4 PRU_RESETz
  J2.6 SoC_I2C0_SCL
  J2.8 SoC_I2C0_SDA
  Thease signals are not connected in this board
- I2C address: 0x53h
- PN#: CRD-081413-A-G
